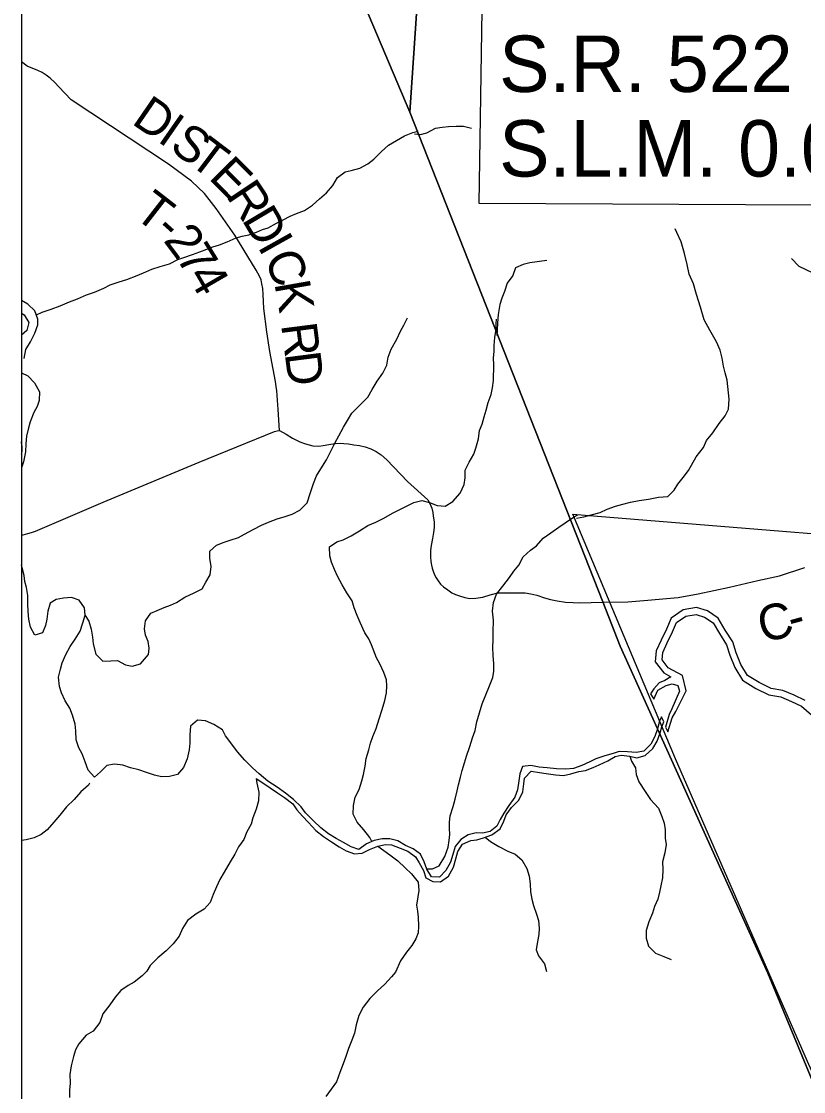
# Model space of a CAD drawing. Extents: x 0 to 82.7, y -0.2 to 22.
# Drawn here: x 2.1 to 3.348, y 16.567 to 18.275 of the extents above; entities that cross this region are included whole.
import ezdxf

# ---------------------------------------------------------------- set-up
doc = ezdxf.new("R2010")
doc.units = 0
for name, color, linetype in [('Default', 7, 'Continuous'), ('GM_X_County_Road', 7, 'Continuous'), ('GM_X_County_Road_Text', 7, 'Continuous'), ('GM_X_Minor_River', 7, 'Continuous'), ('GM_X_Section', 7, 'Continuous'), ('GM_X_Township_Road', 7, 'Continuous'), ('GM_X_Township_Road_Text', 7, 'Continuous'), ('GM_X_Township_Text', 7, 'Continuous'), ('SH_Cut_Line', 7, 'Continuous'), ('SH_Data', 7, 'Continuous')]:
    doc.layers.add(name, color=color, linetype=linetype)

msp = doc.modelspace()

# ---------------------------------------------------------------- linework, layer by layer
at = {"layer": 'Default'}
msp.add_lwpolyline([(3.7948, 18.3961), (3.7869, 17.9798), (2.8306, 17.9843), (2.8367, 18.3961)], dxfattribs=at)
at = {"layer": 'GM_X_County_Road'}
msp.add_lwpolyline([(3.0281, 17.3481), (3.0678, 17.3486), (3.0997, 17.3513), (3.1296, 17.3541), (3.1482, 17.3559), (3.1801, 17.3617), (3.2302, 17.3722), (3.275, 17.3829), (3.3096, 17.3905), (3.3503, 17.4035)], dxfattribs=at)
at = {"layer": 'GM_X_Minor_River'}
for p, q in [((3.1041, 17.202), (3.1094, 17.1935)), ((3.125, 17.1571), (3.1215, 17.1655)), ((3.1277, 17.1487), (3.1317, 17.1411))]:
    msp.add_line(p, q, dxfattribs=at)
for points in [[(2.124, 17.8067), (2.133, 17.8109), (2.1474, 17.8157), (2.1618, 17.8213), (2.1766, 17.8276), (2.1895, 17.832), (2.2039, 17.8384), (2.2165, 17.8428), (2.2317, 17.8495), (2.2415, 17.8544), (2.256, 17.8596), (2.2685, 17.8629), (2.2848, 17.8696), (2.2985, 17.8755), (2.3084, 17.8796), (2.3213, 17.8837), (2.3361, 17.8878), (2.3497, 17.8949), (2.3592, 17.8982), (2.3729, 17.903), (2.3847, 17.9071), (2.3961, 17.9112), (2.4055, 17.9153), (2.4162, 17.9182), (2.4283, 17.9234), (2.4428, 17.9294), (2.4522, 17.9323), (2.4629, 17.9342), (2.475, 17.9386), (2.4845, 17.9427), (2.494, 17.9457), (2.5069, 17.9528), (2.5175, 17.958), (2.5289, 17.964), (2.5392, 17.9684), (2.5517, 17.9733), (2.5643, 17.9815), (2.5757, 17.9917), (2.5868, 18.0014), (2.5967, 18.0131), (2.6044, 18.0256), (2.6169, 18.0349), (2.6264, 18.0368), (2.6401, 18.0408), (2.6526, 18.0476), (2.6625, 18.0551), (2.6747, 18.0671), (2.6858, 18.0776), (2.6987, 18.0851), (2.7113, 18.0922), (2.7246, 18.0978), (2.7333, 18.0997)], [(2.7275, 18.0957), (2.737, 18.0946), (2.7472, 18.097), (2.7608, 18.1044), (2.7714, 18.106), (2.7816, 18.1072), (2.7938, 18.1077), (2.8055, 18.1075), (2.8185, 18.1045)], [(2.9859, 17.4824), (2.9973, 17.4844), (3.009, 17.4876), (3.0238, 17.4915), (3.0348, 17.4966), (3.048, 17.5016), (3.0597, 17.5048), (3.0718, 17.5079), (3.0859, 17.5107), (3.1006, 17.5128), (3.1165, 17.5156), (3.1313, 17.5169), (3.1415, 17.5268), (3.1475, 17.5367), (3.1561, 17.5471), (3.1647, 17.5585), (3.177, 17.5799), (3.1883, 17.5948), (3.1931, 17.6063), (3.2036, 17.6185), (3.2137, 17.6334), (3.223, 17.6457), (3.2286, 17.6563), (3.2296, 17.6719), (3.2263, 17.7026), (3.2228, 17.7144), (3.2204, 17.725), (3.2183, 17.7375), (3.2148, 17.7504), (3.209, 17.7636), (3.1985, 17.7821), (3.1893, 17.7987), (3.1838, 17.8188), (3.1775, 17.8392), (3.1724, 17.8559), (3.1658, 17.8714), (3.1626, 17.8869), (3.1582, 17.9047), (3.1527, 17.9229), (3.1461, 17.938), (3.143, 17.9439)], [(3.3287, 17.8968), (3.3406, 17.8844), (3.362, 17.874), (3.3742, 17.8696), (3.3837, 17.8666), (3.3982, 17.858), (3.4116, 17.8498), (3.4287, 17.8412), (3.4417, 17.8341), (3.4547, 17.8255), (3.4643, 17.8108), (3.4735, 17.7991), (3.4854, 17.789), (3.4969, 17.7796), (3.5072, 17.7737), (3.5195, 17.7593), (3.5279, 17.748), (3.5379, 17.736), (3.5457, 17.7232), (3.5541, 17.7084), (3.5634, 17.6918), (3.5726, 17.6813), (3.5834, 17.6635), (3.5934, 17.653)], [(2.9386, 17.8935), (2.9113, 17.8898), (2.9007, 17.887), (2.8882, 17.8816), (2.8842, 17.8694), (2.8752, 17.8572), (2.8711, 17.8439), (2.8667, 17.8332), (2.8634, 17.8233), (2.8609, 17.8073), (2.8595, 17.7936), (2.8592, 17.783), (2.8589, 17.7735)], [(2.1044, 17.7368), (2.1071, 17.7512), (2.1144, 17.7636), (2.1213, 17.7772), (2.126, 17.7905), (2.1264, 17.7999), (2.1216, 17.8132), (2.1103, 17.8236), (2.1, 17.8295)], [(2.1, 17.8095), (2.1045, 17.8065), (2.112, 17.7944), (2.1089, 17.7815), (2.1, 17.7741)], [(2.2017, 17.3268), (2.2074, 17.3181), (2.2115, 17.3052), (2.2133, 17.2923), (2.2147, 17.2817), (2.2187, 17.2653), (2.23, 17.2539), (2.2425, 17.2549), (2.2535, 17.2552), (2.2663, 17.2483), (2.2769, 17.2459), (2.2902, 17.2496), (2.3028, 17.2647), (2.304, 17.2749), (2.3022, 17.2855), (2.2981, 17.2954), (2.2963, 17.3057), (2.2979, 17.3186), (2.3067, 17.3306), (2.3166, 17.3347), (2.328, 17.3399), (2.3378, 17.3433), (2.3473, 17.3477), (2.361, 17.3564), (2.3755, 17.3631), (2.3884, 17.3694), (2.3941, 17.38), (2.401, 17.3921), (2.403, 17.4049), (2.4009, 17.4182), (2.4006, 17.4296), (2.4113, 17.4394), (2.4238, 17.4442), (2.4333, 17.4472), (2.4466, 17.4516), (2.4561, 17.4568), (2.4697, 17.4643), (2.483, 17.471), (2.4941, 17.4759), (2.5081, 17.4811), (2.521, 17.4848), (2.532, 17.4885), (2.5442, 17.4948), (2.556, 17.5069), (2.5614, 17.5231), (2.5661, 17.5375), (2.5707, 17.55), (2.5807, 17.5651), (2.5868, 17.5756), (2.5941, 17.59), (2.6007, 17.6032), (2.6068, 17.6138), (2.6141, 17.6274), (2.6203, 17.6379), (2.6275, 17.6496), (2.6401, 17.6628), (2.6527, 17.6752), (2.6596, 17.6877), (2.6677, 17.7009), (2.6769, 17.7137), (2.6834, 17.7262), (2.685, 17.739), (2.69, 17.7519), (2.6989, 17.7681), (2.705, 17.7806), (2.7104, 17.7904), (2.7162, 17.8021)], [(2.659, 16.9663), (2.6559, 16.9726), (2.6465, 16.9848), (2.6356, 16.997), (2.6293, 17.01), (2.6302, 17.024), (2.6325, 17.0369), (2.6391, 17.0493), (2.643, 17.0633), (2.6457, 17.0735), (2.6485, 17.0868), (2.6504, 17.0989), (2.6543, 17.1125), (2.6571, 17.1235), (2.6609, 17.1341), (2.666, 17.1466), (2.671, 17.1621), (2.6757, 17.1768), (2.6799, 17.1912), (2.6827, 17.2037), (2.6832, 17.2147), (2.6825, 17.2242), (2.6784, 17.2359), (2.6717, 17.2497), (2.6669, 17.2592), (2.6587, 17.2801), (2.6542, 17.2896), (2.6479, 17.2991), (2.6408, 17.3159), (2.6356, 17.3269), (2.6311, 17.3391), (2.6278, 17.3505), (2.6192, 17.3634), (2.6118, 17.376), (2.6043, 17.3897), (2.5995, 17.4004), (2.5946, 17.4122), (2.5924, 17.4224), (2.5914, 17.4364), (2.6032, 17.4447), (2.6135, 17.4477), (2.626, 17.454), (2.6393, 17.4619), (2.653, 17.4705), (2.6655, 17.4761), (2.6785, 17.4824), (2.6921, 17.4903), (2.7058, 17.4974), (2.7263, 17.5074), (2.7389, 17.5104), (2.7513, 17.5072), (2.7634, 17.5026), (2.7763, 17.5013), (2.7884, 17.5088), (2.7999, 17.522), (2.8064, 17.536), (2.808, 17.5466), (2.8081, 17.5587), (2.8143, 17.5716), (2.822, 17.5844), (2.8254, 17.5942), (2.8293, 17.6086), (2.831, 17.6222), (2.8352, 17.6321), (2.8387, 17.6442), (2.8418, 17.6548), (2.8449, 17.6669), (2.8496, 17.6797), (2.8519, 17.69), (2.8535, 17.7021), (2.8537, 17.7267), (2.8531, 17.7381), (2.8543, 17.7483), (2.8544, 17.7578), (2.8556, 17.7707), (2.8576, 17.7836), (2.8575, 17.7923), (2.858, 17.7996)], [(2.1, 17.7139), (2.1102, 17.7094), (2.1211, 17.698), (2.1289, 17.6839), (2.1281, 17.6702), (2.125, 17.6604), (2.1196, 17.6506), (2.1138, 17.6362), (2.1114, 17.6264), (2.1083, 17.6131), (2.1071, 17.601), (2.1066, 17.5881), (2.1031, 17.5722), (2.1, 17.5624)], [(2.7464, 16.923), (2.7558, 16.9229), (2.7664, 16.9274), (2.7756, 16.9425), (2.7811, 16.9576), (2.7826, 16.9678), (2.7835, 16.9777), (2.7832, 16.9879), (2.7829, 16.9974), (2.7841, 17.0076), (2.7891, 17.022), (2.7923, 17.0341), (2.7954, 17.047), (2.7974, 17.0568), (2.8005, 17.0689), (2.8036, 17.0795), (2.8071, 17.092), (2.8102, 17.1026), (2.8156, 17.1177), (2.8199, 17.1317), (2.8242, 17.1434), (2.8269, 17.1571), (2.8312, 17.1718), (2.8351, 17.1862), (2.8413, 17.2005), (2.8471, 17.2145), (2.8521, 17.2281), (2.854, 17.238), (2.8541, 17.2501), (2.8527, 17.2634), (2.8521, 17.2759), (2.8526, 17.2884), (2.853, 17.3002), (2.8532, 17.3195), (2.8518, 17.3339), (2.8534, 17.3479), (2.8584, 17.3612), (2.868, 17.374), (2.8791, 17.3876), (2.886, 17.3977), (2.8936, 17.4075), (2.9009, 17.4207), (2.9123, 17.4313), (2.9219, 17.438), (2.9326, 17.4501), (2.9451, 17.4591), (2.9577, 17.4677), (2.9676, 17.4748), (2.9809, 17.4838), (2.9877, 17.4874)], [(2.5341, 17.0335), (2.5213, 17.0434), (2.5081, 17.053), (2.4935, 17.0626), (2.4795, 17.0741), (2.4686, 17.084), (2.4566, 17.0959), (2.445, 17.1092), (2.436, 17.1218), (2.4259, 17.1348), (2.421, 17.1447), (2.4071, 17.1531), (2.3939, 17.1589), (2.381, 17.1602), (2.37, 17.1504), (2.3687, 17.1364), (2.3686, 17.1235), (2.3678, 17.1125), (2.3647, 17.0985), (2.3589, 17.0845), (2.3489, 17.0732), (2.3361, 17.0699), (2.3236, 17.0693), (2.3122, 17.0724), (2.2994, 17.0763), (2.2873, 17.0805), (2.2741, 17.0841), (2.2616, 17.0883), (2.2484, 17.0899), (2.2363, 17.0878), (2.226, 17.0776), (2.2164, 17.069), (2.2063, 17.08), (2.2015, 17.0933), (2.197, 17.1063), (2.1918, 17.1158), (2.1874, 17.1287), (2.1867, 17.1427), (2.1857, 17.1538), (2.1813, 17.1682), (2.1772, 17.1792), (2.1701, 17.191), (2.1641, 17.2036), (2.1608, 17.2139), (2.1594, 17.2287), (2.1622, 17.2415), (2.1649, 17.2514), (2.1707, 17.2646), (2.178, 17.2774), (2.1856, 17.2891), (2.194, 17.3019), (2.1979, 17.3152), (2.2018, 17.3273), (2.2008, 17.339), (2.1922, 17.3512), (2.1801, 17.3555), (2.1672, 17.3545), (2.1555, 17.3523), (2.1459, 17.3467), (2.1421, 17.3338), (2.1404, 17.3209), (2.1385, 17.3111), (2.1335, 17.2994), (2.1213, 17.2957), (2.1146, 17.3086), (2.1121, 17.3212), (2.111, 17.3333), (2.11, 17.3458), (2.1101, 17.3587), (2.1083, 17.3716), (2.1057, 17.3811), (2.1043, 17.3906), (2.101, 17.4028), (2.1, 17.4078)], [(3.3507, 17.1912), (3.3333, 17.1997), (3.3152, 17.2074), (3.2962, 17.2106), (3.2773, 17.2199), (3.2585, 17.2314), (3.2479, 17.2489), (3.2405, 17.2672), (3.2353, 17.2847), (3.2232, 17.3038), (3.212, 17.3228), (3.1946, 17.3344), (3.1772, 17.3398), (3.156, 17.3362), (3.1369, 17.3226), (3.1292, 17.3052), (3.1208, 17.2878), (3.1131, 17.2704), (3.1115, 17.253), (3.125, 17.2354), (3.1365, 17.2289)], [(3.1317, 17.1411), (3.1384, 17.1638), (3.1445, 17.174), (3.161, 17.2066), (3.1548, 17.231), (3.1322, 17.2437), (3.1226, 17.2562), (3.1237, 17.2677), (3.1306, 17.2833), (3.139, 17.3007), (3.1456, 17.3156), (3.1602, 17.3259), (3.1765, 17.3287), (3.1899, 17.3245), (3.2039, 17.3152), (3.214, 17.2982), (3.2253, 17.2802), (3.2303, 17.2636), (3.2383, 17.2441), (3.2506, 17.2236), (3.2721, 17.2104), (3.2929, 17.2002), (3.3121, 17.197), (3.3288, 17.1899), (3.3448, 17.1821), (3.3607, 17.1687)], [(3.1365, 17.2289), (3.127, 17.2234), (3.1175, 17.2197), (3.1091, 17.2098), (3.1041, 17.202)], [(3.1094, 17.1935), (3.1156, 17.2081), (3.1291, 17.2155), (3.1385, 17.2182), (3.1476, 17.2154)], [(3.1476, 17.2154), (3.1499, 17.2064), (3.1377, 17.1779), (3.1339, 17.1692), (3.1277, 17.1487)], [(3.1215, 17.1655), (3.118, 17.1586), (3.1149, 17.1461), (3.1106, 17.134), (3.1045, 17.1215), (3.093, 17.1106), (3.0809, 17.1084), (3.0673, 17.1097), (3.054, 17.1098), (3.0445, 17.1068), (3.0309, 17.1031), (3.0168, 17.0983), (3.0073, 17.0935), (2.9944, 17.0879), (2.9811, 17.083), (2.9686, 17.0816), (2.9539, 17.0825), (2.9391, 17.0837), (2.9263, 17.085), (2.9127, 17.0878), (2.8994, 17.0863), (2.8952, 17.0742), (2.8936, 17.0633), (2.8915, 17.0489), (2.8873, 17.0371), (2.8777, 17.0236), (2.8697, 17.0115), (2.8639, 17.0017), (2.8589, 16.9911), (2.8479, 16.9821), (2.8357, 16.9799), (2.8255, 16.9804), (2.813, 16.9771), (2.8012, 16.9696), (2.7924, 16.9583), (2.7882, 16.9454), (2.7846, 16.9333), (2.7774, 16.9201), (2.7674, 16.9096), (2.7542, 16.91), (2.7467, 16.9222), (2.7426, 16.934), (2.7367, 16.9462), (2.7254, 16.9546), (2.7129, 16.96), (2.7005, 16.9677), (2.688, 16.9708), (2.6756, 16.9709), (2.6627, 16.968), (2.6509, 16.9624), (2.6383, 16.9538), (2.6262, 16.9577), (2.6138, 16.9646), (2.6025, 16.9711), (2.5901, 16.9788), (2.5777, 16.988), (2.566, 16.9995), (2.5532, 17.0121), (2.5465, 17.0216), (2.5341, 17.0335)], [(2.4746, 17.0669), (2.4866, 17.0589), (2.4968, 17.052), (2.5088, 17.0443), (2.5201, 17.0366), (2.5329, 17.0267), (2.5393, 17.0171), (2.5483, 17.0068), (2.558, 16.9965), (2.5697, 16.9839), (2.5821, 16.9743), (2.5949, 16.9659), (2.6069, 16.9578), (2.6182, 16.9513), (2.6315, 16.9466), (2.644, 16.9477), (2.6557, 16.9537), (2.6686, 16.9589), (2.6808, 16.9614), (2.6906, 16.961), (2.7042, 16.9559), (2.7167, 16.9509), (2.7287, 16.9421), (2.7347, 16.9326), (2.7414, 16.92), (2.7455, 16.9082), (2.7568, 16.9024), (2.7689, 16.902), (2.7814, 16.9113), (2.7895, 16.9257), (2.793, 16.9385), (2.7965, 16.9503), (2.8038, 16.9623), (2.8171, 16.9679), (2.8269, 16.969), (2.8376, 16.9723), (2.8505, 16.9768), (2.8638, 16.9865), (2.8696, 16.999), (2.8734, 17.0088), (2.8822, 17.0205), (2.8937, 17.0322), (2.9002, 17.0458), (2.9015, 17.0583), (2.9027, 17.0677), (2.9134, 17.0786), (2.927, 17.0763), (2.9375, 17.0747), (2.9523, 17.073), (2.9652, 17.0718), (2.9769, 17.0744), (2.9894, 17.078), (3, 17.0799), (3.0126, 17.0847), (3.0221, 17.0888), (3.0357, 17.0951), (3.0475, 17.1019), (3.057, 17.1041), (3.071, 17.1024), (3.0823, 17.1001), (3.0952, 17.1038), (3.1074, 17.115), (3.1143, 17.1267), (3.1194, 17.1396), (3.1217, 17.1494), (3.125, 17.1571)], [(3.0711, 17.1024), (3.0736, 17.0948), (3.0799, 17.0838), (3.081, 17.0735), (3.0854, 17.0617), (3.0955, 17.0461), (3.1041, 17.0335), (3.1165, 17.0194), (3.1221, 17.0061), (3.1258, 16.9955), (3.1272, 16.9852), (3.1275, 16.9719), (3.1289, 16.9617), (3.1266, 16.9481), (3.123, 16.9337), (3.1233, 16.9219), (3.1228, 16.9083), (3.1205, 16.8954), (3.1185, 16.8856), (3.1154, 16.8746), (3.11, 16.8625), (3.1069, 16.8523), (3.1011, 16.8383), (3.0972, 16.8243), (3.0971, 16.8122), (3.1008, 16.7996), (3.1121, 16.7882), (3.1253, 16.7831), (3.1366, 16.7781)], [(2.2086, 17.0595), (2.2072, 17.0561), (2.1951, 17.0456), (2.184, 17.0336), (2.1722, 17.0219), (2.1611, 17.0083), (2.1519, 16.997), (2.1412, 16.985), (2.1317, 16.9775), (2.1203, 16.9723), (2.1078, 16.969), (2.1, 16.9681)], [(2.4746, 17.0669), (2.4756, 17.0593), (2.4789, 17.0453), (2.4781, 17.0313), (2.4746, 17.018), (2.4691, 17.0044), (2.4664, 16.9938), (2.4595, 16.9817), (2.4549, 16.9696), (2.4465, 16.958), (2.4407, 16.9462), (2.433, 16.9342), (2.4234, 16.9172), (2.4169, 16.9055), (2.4115, 16.8942), (2.4061, 16.8817), (2.4011, 16.8692), (2.3915, 16.8583), (2.3782, 16.8504), (2.3653, 16.8403), (2.3569, 16.8278), (2.3518, 16.8154), (2.3423, 16.8033), (2.3312, 16.792), (2.3179, 16.7808), (2.3057, 16.7687), (2.3003, 16.7593)], [(2.8403, 16.9733), (2.8485, 16.9665), (2.8617, 16.9585), (2.876, 16.9508), (2.8881, 16.9461), (2.8986, 16.9373), (2.9068, 16.9232), (2.9101, 16.9111), (2.9116, 16.8989), (2.9126, 16.886), (2.9144, 16.8743), (2.917, 16.8644), (2.9222, 16.8503), (2.9251, 16.8404), (2.9261, 16.8283), (2.9257, 16.8181), (2.9237, 16.8071), (2.9213, 16.7938), (2.9254, 16.7839), (2.9348, 16.7714), (2.9377, 16.7592)], [(2.6686, 16.9589), (2.6878, 16.9451), (2.7006, 16.9355), (2.7123, 16.9244), (2.7224, 16.9148), (2.7333, 16.9015), (2.734, 16.8882), (2.7327, 16.878), (2.7307, 16.8647), (2.7322, 16.8552), (2.7332, 16.8457), (2.7339, 16.8313), (2.7334, 16.8207), (2.7296, 16.8109), (2.723, 16.8007), (2.7146, 16.7898), (2.7047, 16.7762), (2.697, 16.7579)], [(2.3003, 16.7593), (2.2927, 16.7519), (2.2802, 16.7417), (2.2703, 16.7365), (2.2589, 16.7286), (2.2494, 16.718), (2.241, 16.7059), (2.2299, 16.6912), (2.2253, 16.6776), (2.2143, 16.664), (2.2033, 16.6576), (2.1918, 16.6436), (2.1865, 16.6338), (2.1834, 16.6232), (2.1795, 16.6084), (2.1772, 16.5944), (2.1778, 16.5808), (2.177, 16.5698), (2.1769, 16.558)], [(2.697, 16.7579), (2.6905, 16.7506), (2.6799, 16.7385), (2.6677, 16.7276), (2.6559, 16.7159), (2.6456, 16.702), (2.6387, 16.6887), (2.6341, 16.674), (2.6314, 16.6607), (2.6271, 16.6493), (2.6221, 16.6361), (2.6179, 16.6232), (2.6137, 16.6119), (2.6083, 16.5979), (2.6029, 16.5831), (2.5945, 16.5714), (2.5857, 16.5593)]]:
    msp.add_lwpolyline(points, dxfattribs=at)
at = {"layer": 'GM_X_Section'}
msp.add_lwpolyline([(2.9797, 17.4884), (3.7019, 17.4301), (3.6383, 16.3983), (3.4469, 16.4092), (3.3543, 16.6156), (3.1437, 17.0983)], close=True, dxfattribs=at)
at = {"layer": 'GM_X_Township_Road'}
for points in [[(2.5117, 17.6223), (2.5096, 17.6558), (2.5075, 17.6852), (2.5065, 17.6923), (2.5056, 17.7002), (2.5019, 17.7201), (2.4964, 17.7482), (2.4914, 17.7796), (2.487, 17.8167), (2.4857, 17.8391), (2.4851, 17.8485), (2.4839, 17.8564), (2.4826, 17.8625), (2.4799, 17.8684), (2.4744, 17.8782), (2.4404, 17.9336), (2.4109, 17.9763), (2.3921, 18.0001), (2.3712, 18.0197), (2.3348, 18.0469), (2.1795, 18.1497), (2.1598, 18.1704), (2.1535, 18.1774), (2.1459, 18.1843), (2.1396, 18.1889), (2.1329, 18.1935), (2.1262, 18.1965), (2.1094, 18.2036), (2.1, 18.2101)], [(2.1, 17.455), (2.1026, 17.4555), (2.1103, 17.4576), (2.116, 17.4592), (2.1225, 17.4615), (2.2307, 17.508), (2.3836, 17.5717), (2.504, 17.6203), (2.5081, 17.6217), (2.5117, 17.6223)], [(2.5117, 17.6223), (2.5224, 17.6161), (2.5326, 17.61), (2.5442, 17.6043), (2.5532, 17.6008), (2.5653, 17.5978), (2.5745, 17.597), (2.5818, 17.5981), (2.5906, 17.5997), (2.6007, 17.6016), (2.6086, 17.602), (2.6143, 17.6016), (2.6218, 17.601), (2.6304, 17.5995), (2.6394, 17.5981), (2.6486, 17.596), (2.6578, 17.593), (2.666, 17.5886), (2.674, 17.5832), (2.683, 17.5752), (2.7163, 17.5409), (2.7485, 17.5116), (2.7519, 17.5055), (2.7548, 17.498), (2.7565, 17.4915), (2.7573, 17.4852), (2.7588, 17.4766), (2.7588, 17.4674), (2.7575, 17.4592), (2.7558, 17.45), (2.754, 17.4387), (2.7529, 17.4306), (2.7529, 17.4207), (2.7535, 17.413), (2.7544, 17.4073), (2.7554, 17.4027), (2.7575, 17.3962), (2.7598, 17.391), (2.7617, 17.387), (2.7651, 17.3824), (2.769, 17.377), (2.7738, 17.3726), (2.7805, 17.368), (2.787, 17.3633), (2.7925, 17.3604), (2.799, 17.3583), (2.8078, 17.3558), (2.8157, 17.3543), (2.8254, 17.3548), (2.8364, 17.3564), (2.8482, 17.3598), (2.8603, 17.3629), (2.875, 17.3631), (2.8909, 17.3631), (2.9041, 17.3629), (2.9129, 17.3617), (2.9223, 17.3592), (2.9346, 17.3552), (2.9445, 17.3525), (2.9552, 17.3502), (2.9681, 17.3485), (2.9805, 17.3476), (2.9899, 17.3472), (3.0281, 17.3481)], [(2.1, 17.5842), (2.101, 17.5886), (2.1014, 17.5964), (2.1004, 17.6023), (2.1, 17.6043)]]:
    msp.add_lwpolyline(points, dxfattribs=at)
at = {"layer": 'GM_X_Township_Text'}
for points in [[(6.1272, 20.9), (2.1, 20.9), (2.1, 19.5964), (2.2742, 19.1826), (2.3145, 19.0873), (2.397, 18.8926), (2.4438, 18.782), (2.7199, 18.1299), (2.7784, 18.9951), (2.7788, 19.0007), (2.8288, 19.7415), (2.8645, 20.2693), (2.8645, 20.2703), (2.8651, 20.279), (2.884, 20.5583), (3.179, 20.5374), (3.6288, 20.5056), (5.9672, 20.3493), (5.9756, 20.3782)], [(2.1, 19.5964), (2.1, 14.1), (2.4652, 14.1), (3.1288, 14.3932), (3.6092, 14.6054), (3.7187, 14.6543), (4.1209, 14.8338), (3.8036, 15.5496), (3.6125, 15.9807), (3.4071, 16.476), (3.2909, 16.7562), (3.0556, 17.2782), (3.0279, 17.3486), (2.7199, 18.1299), (2.4438, 18.782), (2.397, 18.8926), (2.3145, 19.0873), (2.2742, 19.1826)]]:
    msp.add_lwpolyline(points, close=True, dxfattribs=at)
msp.add_lwpolyline([(5.9672, 20.3493), (3.6288, 20.5056), (3.179, 20.5374), (2.884, 20.5583), (2.8651, 20.279), (2.8645, 20.2703), (2.8645, 20.2693), (2.8288, 19.7415), (2.7788, 19.0007), (2.7784, 18.9951), (2.7199, 18.1299), (3.0279, 17.3486), (3.0556, 17.2782), (3.2909, 16.7562), (3.4071, 16.476), (3.6125, 15.9807), (3.8036, 15.5496), (4.1209, 14.8338)], dxfattribs=at)
at = {"layer": 'SH_Cut_Line'}
for points in [[(4.1209, 14.8338), (3.8036, 15.5496), (3.6125, 15.9807), (3.4071, 16.476), (3.2909, 16.7562), (3.0556, 17.2782), (3.0279, 17.3486), (2.7199, 18.1299), (2.7784, 18.9951), (2.7788, 19.0007), (2.8288, 19.7415), (2.8645, 20.2693), (2.8645, 20.2703), (2.8651, 20.279), (2.884, 20.5583), (3.179, 20.5374), (3.6288, 20.5056), (5.9672, 20.3493), (5.9756, 20.3782), (6.1272, 20.9), (2.1, 20.9), (2.1, 14.1)], [(8.9, 14.1), (8.9, 20.9), (6.1272, 20.9), (5.9756, 20.3782), (5.9672, 20.3493), (3.6288, 20.5056), (3.179, 20.5374), (2.884, 20.5583), (2.8651, 20.279), (2.8645, 20.2703), (2.8645, 20.2693), (2.8288, 19.7415), (2.7788, 19.0007), (2.7784, 18.9951), (2.7199, 18.1299), (3.0279, 17.3486), (3.0556, 17.2782), (3.2909, 16.7562), (3.4071, 16.476), (3.6125, 15.9807), (3.8036, 15.5496), (4.1209, 14.8338)]]:
    msp.add_lwpolyline(points, dxfattribs=at)
at = {"layer": 'SH_Data'}
msp.add_line((2.1, 20.9), (2.1, 14.1), dxfattribs=at)

# ---------------------------------------------------------------- texts
at = {"layer": 'Default'}
for s, p in [('S.R. 522', (2.8624, 18.1623)), ('S.L.M. 0.000', (2.8624, 18.0273))]:
    msp.add_text(s, height=0.09, dxfattribs=at).set_placement(p)
at = {"layer": 'GM_X_County_Road_Text'}
for s, rotation, p in [('C', 13.065, (3.2824, 17.2833)), ('-', 15.449, (3.3304, 17.2945))]:
    msp.add_text(s, height=0.0568, rotation=rotation, dxfattribs=at).set_placement(p)
at = {"layer": 'GM_X_Township_Road_Text'}
for s, rotation, p in [('D', 325.5249, (2.2742, 18.1126)), ('I', 325.1429, (2.3154, 18.0844)), ('S', 324.1964, (2.3343, 18.0712)), ('T', 322.9133, (2.3651, 18.049)), ('E', 314.6561, (2.3974, 18.0248)), ('R', 303.5905, (2.4255, 17.9968)), ('T', 322.1598, (2.2775, 17.9642)), ('D', 300.6698, (2.4509, 17.9586)), ('-', 317.9461, (2.3102, 17.9389)), ('2', 306.669, (2.3255, 17.9254)), ('I', 299.254, (2.4762, 17.9159)), ('7', 301.6863, (2.3457, 17.8984)), ('C', 292.2138, (2.4868, 17.8972)), ('4', 300.1315, (2.3639, 17.869)), ('K', 279.9585, (2.5035, 17.8571)), ('R', 277.3027, (2.5143, 17.7911)), ('D', 277.3017, (2.5202, 17.7449))]:
    msp.add_text(s, height=0.0568, rotation=rotation, dxfattribs=at).set_placement(p)

doc.saveas('drawing.dxf')
